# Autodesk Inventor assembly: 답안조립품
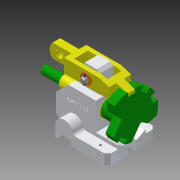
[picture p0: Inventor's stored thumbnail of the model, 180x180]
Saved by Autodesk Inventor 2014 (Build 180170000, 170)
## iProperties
Created: 2016-11
Part Number: 답안조립품
Document SubType Name: Assembly
Designer: owner
Author: owner
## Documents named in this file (8)
- C:\Users\owner\Desktop\461107V1002\답안조립품.iam
- C:\Users\owner\Desktop\461107V1002\본체.ipt
- C:\Users\owner\Desktop\461107V1002\부시.ipt
- C:\Users\owner\Desktop\461107V1002\분할축.ipt
- C:\Users\owner\Desktop\461107V1002\분할대.ipt
- C:\Users\owner\Desktop\461107V1002\클레비스핀.ipt
- C:\Users\owner\Desktop\461107V1002\와셔.ipt
- C:\Users\owner\Desktop\461107V1002\원통형핀.ipt
